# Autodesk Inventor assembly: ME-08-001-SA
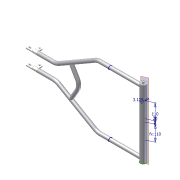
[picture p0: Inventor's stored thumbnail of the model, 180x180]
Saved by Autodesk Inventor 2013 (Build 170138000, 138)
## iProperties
Shininess: 20.0
Length Units: 11269
Angle Units: 11279
Time Units: 11290
Mass Units: 11283
Length Display Precision: 3
Angle Display Precision: 2
Created: 2001-04
Part Number: ME-08-001-SA
Document SubType Name: Baugruppe
Designer: dl
Density: 0.0
Volumn: 0.0
Area: 0.0
PropertySet Name: Model Information
Control State: 0
Master: False
Checked Out: False
Author: dl
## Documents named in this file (6)
- C:\Webworld\Webworld2014\ATC2013\Assemblies\ATC-Baby Carriage\1-BASE FRAME\ME-08-001-SA.iam
- C:\Webworld\Webworld2014\ATC2013\Assemblies\ATC-Baby Carriage\1-BASE FRAME\End_piece.ipt
- C:\Webworld\Webworld2014\ATC2013\Assemblies\ATC-Baby Carriage\1-BASE FRAME\Axis_frame_half.ipt
- C:\Webworld\Webworld2014\ATC2013\Assemblies\ATC-Baby Carriage\1-BASE FRAME\Main_axis.ipt
- C:\Webworld\Webworld2014\ATC2013\Assemblies\ATC-Baby Carriage\1-BASE FRAME\Bearing_sleve.ipt
- C:\Webworld\Webworld2014\ATC2013\Assemblies\ATC-Baby Carriage\1-BASE FRAME\Cross_girder.ipt
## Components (8 placed, 5 different names)
1. End_piece:1 — Flush:1, Mate:1, Flush:2, Insert:1, Mate:3, Mate:4, Mate:6
2. End_piece:2 — Flush:1, Mate:1, Flush:2, Insert:2
3. Main_axis:1 — Mate:3, Mate:4, Insert:3, Insert:4, Mate:8, Angle:1
4. Axis_frame_half:1 — Insert:1, Mate:2, Mate:9
5. Axis_frame_half:2 — Insert:2, Mate:2, Mate:8, Mate:10
6. Bearing_sleve:1 — Insert:3
7. Bearing_sleve:2 — Insert:4
8. Cross_girder:1 — Mate:6, Mate:9, Mate:10
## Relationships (15: Mate 8, Insert 4, Flush 2, Angle 1)
- Flush:1: End_piece:1 ↔ End_piece:2
- Mate:1: End_piece:1 ↔ End_piece:2
- Flush:2: End_piece:1 ↔ End_piece:2
- Insert:1: End_piece:1 ↔ Axis_frame_half:1
- Insert:2: End_piece:2 ↔ Axis_frame_half:2
- Mate:2: Axis_frame_half:1 ↔ Axis_frame_half:2
- Mate:3: End_piece:1 ↔ Main_axis:1
- Mate:4: End_piece:1 ↔ Main_axis:1
- Insert:3: Main_axis:1 ↔ Bearing_sleve:1
- Insert:4: Main_axis:1 ↔ Bearing_sleve:2
- Mate:6: End_piece:1 ↔ Cross_girder:1
- Mate:8: Main_axis:1 ↔ Axis_frame_half:2
- Mate:9: Axis_frame_half:1 ↔ Cross_girder:1
- Mate:10: Axis_frame_half:2 ↔ Cross_girder:1
- Angle:1: Main_axis:1
